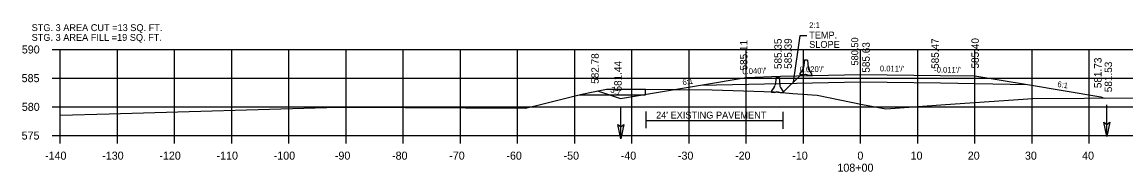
# Model space of a CAD drawing. Extents: x 642114 to 642416, y 286928 to 293347.
# Drawn here: x 642113.6 to 642306.6, y 288515.1 to 288541.2 of the extents above; entities that cross this region are included whole.
import ezdxf

# ---------------------------------------------------------------- set-up
doc = ezdxf.new("R2010")
doc.units = 0
for name, color, linetype in [('59', 7, 'Continuous'), ('Level 43', 7, 'Continuous'), ('Level 58', 7, 'Continuous'), ('R_Axis', 7, 'Continuous'), ('R_Axis Annot', 7, 'Continuous'), ('R_Draft', 7, 'Continuous'), ('R_Exist Surface', 7, 'Continuous'), ('R_Exist Surface Annot', 7, 'Continuous'), ('R_Fin Surface', 7, 'Continuous'), ('R_Grid', 7, 'Continuous'), ('R_MOT Barrier', 7, 'Continuous'), ('R_Xsect Elev', 7, 'Continuous'), ('R_Xsect Slope', 7, 'Continuous')]:
    doc.layers.add(name, color=color, linetype=linetype)

# ---------------------------------------------------------------- blocks, each defined once
blk = doc.blocks.new('BARRIER WALL X-SECTION')
at = {"layer": 'R_MOT Barrier'}
for p, q in [((0.8, 2.59), (0.63, 1.29)), ((0.8, 2.59), (0.87, 2.65)), ((0.87, 2.65), (1.24, 2.64)), ((1.24, 2.64), (1.31, 2.58)), ((1.31, 2.58), (1.42, 1.27)), ((0.48, 0.9), (0, 0.25)), ((0, 0.25), (0, 0)), ((0.5, -0.01), (0, 0)), ((0.5, -0.01), (1, 0.15)), ((1, 0.15), (1.5, -0.03)), ((1.56, 0.88), (2, 0.21)), ((2, 0.21), (2, -0.04)), ((1.5, -0.03), (2, -0.04))]:
    blk.add_line(p, q, dxfattribs=at)
for centre, start, end in [((-0.2, 1.39), 323.8622, 352.8452), ((2.25, 1.34), 184.8632, 213.8462)]:
    blk.add_arc(centre, 0.833, start, end, dxfattribs=at)
blk = doc.blocks.new('FA')
at = {"layer": 'Level 43'}
blk.add_lwpolyline([(7.94, 0), (0, 0)], dxfattribs=at)
at = {"layer": 'Level 58'}
blk.add_lwpolyline([(4.34, 0.75), (7.94, 0), (4.34, -0.75), (4.94, 0)], close=True, dxfattribs=at)

msp = doc.modelspace()

# ---------------------------------------------------------------- linework, layer by layer
at = {"layer": 'R_Axis'}
for p, q in [((642118.84, 288536.41), (642120.24, 288536.41)), ((642120.24, 288521.41), (642120.24, 288536.41)), ((642118.84, 288531.41), (642120.24, 288531.41)), ((642118.84, 288526.41), (642120.24, 288526.41)), ((642118.84, 288521.41), (642120.24, 288521.41)), ((642120.24, 288521.41), (642400.24, 288521.41)), ((642120.24, 288520.01), (642120.24, 288521.41)), ((642130.24, 288520.01), (642130.24, 288521.41)), ((642140.24, 288520.01), (642140.24, 288521.41)), ((642150.24, 288520.01), (642150.24, 288521.41)), ((642160.24, 288520.01), (642160.24, 288521.41)), ((642170.24, 288520.01), (642170.24, 288521.41)), ((642180.24, 288520.01), (642180.24, 288521.41)), ((642190.24, 288520.01), (642190.24, 288521.41)), ((642200.24, 288520.01), (642200.24, 288521.41)), ((642210.24, 288520.01), (642210.24, 288521.41)), ((642220.24, 288520.01), (642220.24, 288521.41)), ((642230.24, 288520.01), (642230.24, 288521.41)), ((642240.24, 288520.01), (642240.24, 288521.41)), ((642250.24, 288520.01), (642250.24, 288521.41)), ((642260.24, 288520.01), (642260.24, 288521.41)), ((642270.24, 288520.01), (642270.24, 288521.41)), ((642280.24, 288520.01), (642280.24, 288521.41)), ((642290.24, 288520.01), (642290.24, 288521.41)), ((642300.24, 288520.01), (642300.24, 288521.41))]:
    msp.add_line(p, q, dxfattribs=at)
at = {"layer": 'R_Exist Surface'}
msp.add_lwpolyline([(642232.25, 288530.18), (642246.24, 288530.46), (642260.24, 288530.74), (642274.24, 288530.58), (642289.4, 288530.28)], dxfattribs=at)
at = {"layer": 'R_Exist Surface Annot'}
msp.add_lwpolyline([(642120.24, 288524.97), (642128.82, 288525.18), (642168.88, 288526.35), (642172.53, 288526.36), (642180.57, 288526.3), (642201.64, 288526.16), (642204.73, 288526.94), (642211.46, 288528.63), (642213.45, 288529.02), (642215.8, 288529.5), (642219.9, 288529.52), (642222.64, 288529.52), (642227.61, 288529.43), (642234.27, 288529.39), (642239.76, 288529.18), (642245.11, 288529.01), (642248.4, 288528.75), (642252.65, 288528.42), (642260.57, 288526.84), (642264.64, 288526.07), (642275.08, 288526.81), (642290.39, 288527.86), (642326.58, 288528.08), (642332.08, 288528.11)], dxfattribs=at)
at = {"layer": 'R_Fin Surface'}
for points in [[(642214.23, 288529.18), (642218.24, 288527.85), (642232.25, 288530.18), (642240.24, 288531.51), (642246.24, 288531.75), (642260.24, 288532.03), (642274.24, 288531.87)], [(642274.24, 288531.87), (642280.24, 288531.8), (642289.4, 288530.28), (642302.24, 288528.14), (642302.84, 288527.94)]]:
    msp.add_lwpolyline(points, dxfattribs=at)
at = {"layer": 'R_Grid'}
for p, q in [((642120.24, 288536.41), (642400.24, 288536.41)), ((642120.24, 288521.41), (642120.24, 288536.41)), ((642130.24, 288521.41), (642130.24, 288536.41)), ((642140.24, 288521.41), (642140.24, 288536.41)), ((642150.24, 288521.41), (642150.24, 288536.41)), ((642160.24, 288521.41), (642160.24, 288536.41)), ((642170.24, 288521.41), (642170.24, 288536.41)), ((642180.24, 288521.41), (642180.24, 288536.41)), ((642190.24, 288521.41), (642190.24, 288536.41)), ((642200.24, 288521.41), (642200.24, 288536.41)), ((642210.24, 288521.41), (642210.24, 288536.41)), ((642220.24, 288521.41), (642220.24, 288536.41)), ((642230.24, 288521.41), (642230.24, 288536.41)), ((642240.24, 288521.41), (642240.24, 288536.41)), ((642250.24, 288521.41), (642250.24, 288536.41)), ((642260.24, 288521.41), (642260.24, 288536.41)), ((642270.24, 288521.41), (642270.24, 288536.41)), ((642280.24, 288521.41), (642280.24, 288536.41)), ((642290.24, 288521.41), (642290.24, 288536.41)), ((642300.24, 288521.41), (642300.24, 288536.41)), ((642120.24, 288531.41), (642400.24, 288531.41)), ((642120.24, 288526.41), (642400.24, 288526.41)), ((642120.24, 288521.41), (642400.24, 288521.41))]:
    msp.add_line(p, q, dxfattribs=at)
at = {"layer": 'R_Xsect Elev'}
for p, q in [((642246.66, 288528.89), (642249.59, 288531.82)), ((642222.71, 288522.69), (642222.71, 288525.61)), ((642222.71, 288524.04), (642246.71, 288524.04)), ((642246.71, 288522.6), (642246.71, 288525.52))]:
    msp.add_line(p, q, dxfattribs=at)
for points in [[(642249.62, 288538.78), (642248.46, 288530.71)], [(642250.84, 288538.78), (642249.62, 288538.78)], [(642211.01, 288528.52), (642222.64, 288528.52), (642222.64, 288529.52)]]:
    msp.add_lwpolyline(points, dxfattribs=at)

# ---------------------------------------------------------------- block references
for p in [(642249.62, 288531.98), (642244.66, 288528.93)]:
    msp.add_blockref('BARRIER WALL X-SECTION', p, dxfattribs=at)
at = {"layer": 'R_Xsect Elev', "xscale": 0.7, "yscale": 0.7}
for p, rotation in [((642218.3, 288526.37), -90.0000000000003), ((642303.32, 288526.79), -90.00000000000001)]:
    msp.add_blockref('FA', p, dxfattribs=dict(at, rotation=rotation))

# ---------------------------------------------------------------- texts
at = {"layer": '59'}
for s, p in [(' 585.11', (642240.44, 288532.27)), (' 585.35', (642246.44, 288532.51)), (' 585.39', (642248.2, 288532.55)), (' 585.63', (642261.84, 288531.88)), (' 585.47', (642273.92, 288532.54)), (' 582.78', (642214.43, 288529.94)), (' 581.44', (642218.44, 288528.6))]:
    msp.add_text(s, height=1.3, rotation=90, dxfattribs=at).set_placement(p)
at = {"layer": 'R_Axis Annot'}
for s, p in [('590', (642113.52, 288535.71)), ('585', (642113.49, 288530.71)), ('580', (642113.52, 288525.71)), ('575', (642113.49, 288520.71)), ('-140', (642117.58, 288517.21)), ('-130', (642127.58, 288517.21)), ('-120', (642137.58, 288517.21)), ('-110', (642147.58, 288517.21)), ('-100', (642157.58, 288517.21)), ('-90', (642168.28, 288517.21)), ('-80', (642178.28, 288517.21)), ('-70', (642188.28, 288517.21)), ('-60', (642198.28, 288517.21)), ('-50', (642208.28, 288517.21)), ('-40', (642218.28, 288517.21)), ('-30', (642228.28, 288517.21)), ('-20', (642238.28, 288517.21)), ('-10', (642248.28, 288517.21)), ('0', (642259.68, 288517.21)), ('10', (642268.98, 288517.21)), ('20', (642278.98, 288517.21)), ('30', (642288.98, 288517.21)), ('40', (642298.98, 288517.21)), ('108+00', (642256.18, 288515.11))]:
    msp.add_text(s, height=1.4, dxfattribs=at).set_placement(p)
at = {"layer": 'R_Draft'}
for s, p in [('STG. 3 AREA CUT =13 SQ. FT.', (642115.24, 288539.61)), ('STG. 3 AREA FILL =19 SQ. FT.', (642115.24, 288537.91))]:
    msp.add_text(s, height=1.2, dxfattribs=at).set_placement(p)
at = {"layer": 'R_Xsect Elev'}
for s, p in [('TEMP.', (642251.24, 288538.31)), ('SLOPE', (642251.24, 288536.68)), ("24' EXISTING PAVEMENT", (642224.46, 288524.37))]:
    msp.add_text(s, height=1.2, dxfattribs=at).set_placement(p)
for s, height, p in [('580.50', 1.2, (642259.82, 288533.61)), (' 585.40', 1.3, (642280.92, 288532.6)), (' 581.73', 1.3, (642302.38, 288529.19)), (' 581.53', 1.3, (642304.22, 288528.48))]:
    msp.add_text(s, height=height, rotation=90, dxfattribs=at).set_placement(p)
at = {"layer": 'R_Xsect Slope'}
for s, rotation, p in [('2:1', 0.32, (642251.25, 288540.15)), ("0.040'/'", 2.2906, (642239.57, 288532.09)), ("0.020'/'", 1.1458, (642249.58, 288532.42)), ("0.011'/'", 359.3441, (642263.6, 288532.6)), ("-0.011'/'", 359.3447, (642273.09, 288532.39)), ('6:1', 9.4642, (642229.16, 288530.17)), ('3:1', 341.5668, (642216.39, 288528.99)), ('6:1', 350.5358, (642294.6, 288529.91))]:
    msp.add_text(s, height=1, rotation=rotation, dxfattribs=at).set_placement(p)

doc.saveas('drawing.dxf')
